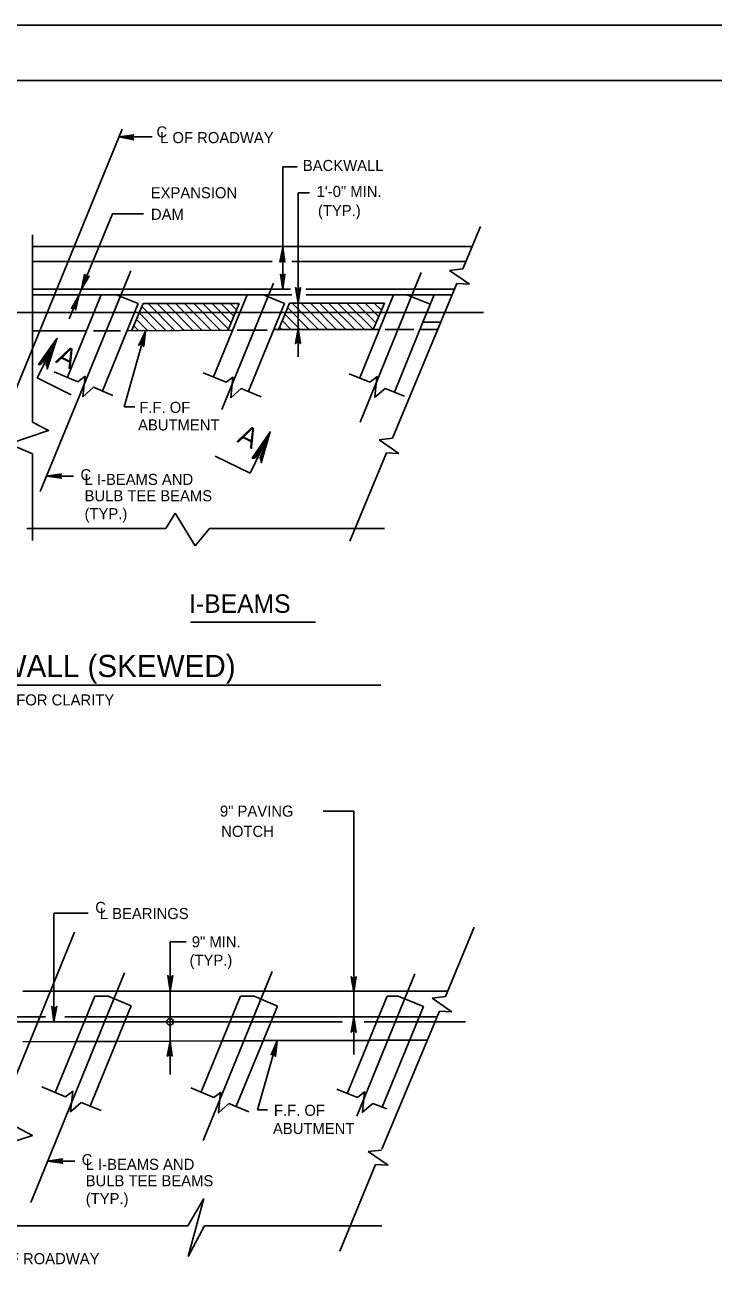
# Model space of a CAD drawing. Extents: x 640058 to 640913, y 299411 to 300005.
# Drawn here: x 640298.9 to 640485.4, y 299663.2 to 300005.4 of the extents above; entities that cross this region are included whole.
import ezdxf

# ---------------------------------------------------------------- set-up
doc = ezdxf.new("R2010")
doc.units = 0
doc.layers.add('1', color=7, linetype='Continuous')
doc.layers.add('PLT-BNDY', color=7, linetype='Continuous')

msp = doc.modelspace()

# ---------------------------------------------------------------- linework, layer by layer
at = {"layer": '1'}
for p, q in [((640097.79, 299990.45), (640883.79, 299990.45)), ((640325.16, 299977.3), (640274.71, 299854.35)), ((640324.26, 299975.2), (640333.26, 299975.2)), ((640368.66, 299945.35), (640368.66, 299967.1)), ((640368.66, 299967.1), (640372.56, 299967.1)), ((640372.86, 299930.2), (640372.86, 299960.05)), ((640372.86, 299960.05), (640375.86, 299960.05)), ((640310.83, 299925.89), (640322.5, 299954.33)), ((640330.9, 299954.33), (640322.5, 299954.33)), ((640417.46, 299939.47), (640422.21, 299950.9)), ((640300.86, 299897.95), (640300.86, 299948.65)), ((640419.97, 299945.5), (640300.86, 299945.5)), ((640368.66, 299933.95), (640368.66, 299945.35)), ((640368.66, 299933.95), (640368.66, 299945.35)), ((640365.82, 299941.45), (640300.86, 299941.45)), ((640302.96, 299879.2), (640327.48, 299938.91)), ((640418.28, 299941.45), (640371.08, 299941.45)), ((640413.84, 299939.03), (640417.46, 299939.47)), ((640419.22, 299935.33), (640413.84, 299939.03)), ((640352.16, 299901.4), (640366.11, 299935.6)), ((640389.64, 299897.96), (640406.18, 299938.44)), ((640398.38, 299893.57), (640415.82, 299935.53)), ((640415.82, 299935.53), (640419.22, 299935.33)), ((640370.79, 299933.95), (640300.86, 299933.95)), ((640371.1, 299932.45), (640300.86, 299932.45)), ((640310.31, 299910.1), (640319.46, 299932.45)), ((640323.66, 299932.45), (640319.46, 299932.45)), ((640323.66, 299932.45), (640329.51, 299930.05)), ((640349.91, 299910.25), (640359.06, 299932.45)), ((640363.41, 299932.45), (640359.06, 299932.45)), ((640363.41, 299932.45), (640369.11, 299930.05)), ((640415.17, 299933.95), (640374.88, 299933.95)), ((640414.54, 299932.45), (640375.02, 299932.45)), ((640389.51, 299909.95), (640398.66, 299932.45)), ((640402.26, 299932.45), (640398.66, 299932.45)), ((640402.26, 299932.45), (640408.63, 299929.93)), ((640409.65, 299932.45), (640406.64, 299925.02)), ((640329.51, 299930.05), (640319.76, 299906.2)), ((640327.8, 299922.85), (640330.8, 299930.05)), ((640336.86, 299922.89), (640330.48, 299929.28)), ((640330.8, 299930.05), (640356.81, 299930.05)), ((640339.46, 299922.77), (640332.18, 299930.05)), ((640341.92, 299922.78), (640334.65, 299930.05)), ((640344.38, 299922.8), (640337.13, 299930.05)), ((640346.84, 299922.81), (640339.6, 299930.05)), ((640349.18, 299922.95), (640342.08, 299930.05)), ((640351.64, 299922.96), (640344.55, 299930.05)), ((640353.93, 299923.14), (640347.02, 299930.05)), ((640354.66, 299924.89), (640349.5, 299930.05)), ((640355.39, 299926.64), (640351.97, 299930.05)), ((640356.81, 299930.05), (640353.86, 299922.97)), ((640356.12, 299928.38), (640354.45, 299930.05)), ((640369.11, 299930.05), (640359.36, 299906.35)), ((640367.49, 299922.97), (640370.44, 299930.2)), ((640375.92, 299922.98), (640369.94, 299928.96)), ((640370.44, 299930.2), (640378.11, 299930.2)), ((640378.39, 299922.99), (640371.18, 299930.2)), ((640371.36, 299930.2), (640374.36, 299930.2)), ((640372.86, 299923), (640372.86, 299930.2)), ((640380.87, 299922.99), (640373.65, 299930.2)), ((640383.34, 299922.99), (640376.13, 299930.2)), ((640376.91, 299930.2), (640396.19, 299930.2)), ((640385.81, 299922.99), (640378.6, 299930.2)), ((640388.28, 299923), (640381.08, 299930.2)), ((640390.76, 299923), (640383.55, 299930.2)), ((640393.2, 299923.03), (640386.03, 299930.2)), ((640393.93, 299924.77), (640388.5, 299930.2)), ((640394.66, 299926.52), (640390.98, 299930.2)), ((640396.19, 299930.2), (640393.19, 299923)), ((640395.39, 299928.27), (640393.45, 299930.2)), ((640396.11, 299930.01), (640395.93, 299930.2)), ((640175.2, 299927.65), (640377.06, 299927.65)), ((640331.93, 299922.87), (640329.02, 299925.78)), ((640334.4, 299922.88), (640329.75, 299927.53)), ((640370.98, 299922.98), (640368.51, 299925.45)), ((640373.45, 299922.98), (640369.22, 299927.21)), ((640376.91, 299927.65), (640423.03, 299927.65)), ((640300.86, 299922.7), (640315.41, 299922.7)), ((640317.43, 299922.7), (640324.74, 299922.7)), ((640325.7, 299902.13), (640331.46, 299922.55)), ((640326.36, 299922.7), (640355.1, 299922.85)), ((640329.47, 299922.86), (640328.29, 299924.03)), ((640356.35, 299922.85), (640364.42, 299922.85)), ((640366.21, 299923), (640394.76, 299923)), ((640368.51, 299922.97), (640367.79, 299923.69)), ((640371.36, 299923), (640374.36, 299923)), ((640372.86, 299915.65), (640372.86, 299923.3)), ((640396.38, 299923), (640404.18, 299923)), ((640406.64, 299925.02), (640398.96, 299906.05)), ((640405.82, 299923), (640410.62, 299923)), ((640406.64, 299925.02), (640411.45, 299925.02)), ((640307.51, 299920.63), (640302.15, 299909.91)), ((640306.71, 299911.6), (640313.16, 299908.9)), ((640302.15, 299909.91), (640311.3, 299905.34)), ((640347.06, 299911.3), (640353.36, 299908.75)), ((640386.66, 299911), (640392.21, 299908.75)), ((640317.36, 299907.4), (640322.61, 299905.15)), ((640357.41, 299907.1), (640362.81, 299904.85)), ((640396.41, 299907.1), (640401.66, 299905)), ((640325.7, 299902.13), (640328.55, 299902.13)), ((640365.21, 299895.35), (640359.86, 299884.14)), ((640394.76, 299893.13), (640398.38, 299893.57)), ((640400.14, 299889.43), (640394.76, 299893.13)), ((640300.86, 299865.85), (640300.86, 299889.4)), ((640350.36, 299888.76), (640359.86, 299884.14)), ((640386.82, 299865.73), (640396.75, 299889.63)), ((640396.75, 299889.63), (640400.14, 299889.43)), ((640304.66, 299883.34), (640312.01, 299883.34)), ((640337, 299869.13), (640339.55, 299873.33)), ((640339.55, 299873.33), (640344.95, 299864.48)), ((640299.35, 299869.13), (640337, 299869.13)), ((640344.95, 299864.48), (640348.85, 299869.13)), ((640348.85, 299869.13), (640396.2, 299869.13)), ((640343.71, 299843.8), (640377.57, 299843.8)), ((640171.38, 299826.75), (640395.26, 299826.75)), ((640387.94, 299792.54), (640379.61, 299792.54)), ((640387.94, 299743.84), (640387.94, 299792.54)), ((640306.68, 299764.99), (640315.93, 299764.99)), ((640306.68, 299735.53), (640306.68, 299764.99)), ((640412.72, 299742.36), (640420.53, 299761.14)), ((640275.18, 299669.17), (640312.23, 299759.85)), ((640338.12, 299757.19), (640342.5, 299757.19)), ((640338.12, 299743.84), (640338.12, 299757.19)), ((640300.38, 299686.57), (640325.79, 299748.84)), ((640347.06, 299703.39), (640365.75, 299749.16)), ((640388.73, 299710.01), (640404.44, 299748.55)), ((640413.34, 299743.84), (640298.28, 299743.84)), ((640338.12, 299735.53), (640338.12, 299743.84)), ((640387.94, 299736.88), (640387.94, 299743.84)), ((640306.98, 299716.42), (640317.73, 299742.47)), ((640321.34, 299742.47), (640317.73, 299742.47)), ((640321.34, 299742.47), (640327.58, 299739.82)), ((640346.58, 299716.57), (640357.17, 299742.47)), ((640360.94, 299742.47), (640357.17, 299742.47)), ((640360.94, 299742.47), (640367.19, 299739.81)), ((640386.18, 299716.27), (640396.93, 299742.47)), ((640399.94, 299742.47), (640396.93, 299742.47)), ((640399.94, 299742.47), (640406.78, 299739.67)), ((640409.1, 299741.92), (640412.72, 299742.36)), ((640414.48, 299738.22), (640409.1, 299741.92)), ((640327.58, 299739.82), (640316.43, 299712.52)), ((640367.19, 299739.81), (640356.03, 299712.67)), ((640395.53, 299701), (640411.09, 299738.42)), ((640406.78, 299739.67), (640395.63, 299712.37)), ((640411.09, 299738.42), (640414.48, 299738.22)), ((640177.72, 299735.53), (640384.72, 299735.53)), ((640304.36, 299736.88), (640183.16, 299736.88)), ((640410.45, 299736.88), (640309.64, 299736.88)), ((640338.12, 299730.37), (640338.12, 299735.53)), ((640387.94, 299726.68), (640387.94, 299736.88)), ((640390.73, 299735.53), (640418.2, 299735.53)), ((640298.28, 299730.07), (640312.68, 299730.22)), ((640312.68, 299730.22), (640323.66, 299730.22)), ((640323.78, 299730.22), (640352.43, 299730.37)), ((640338.12, 299721.26), (640338.12, 299730.3)), ((640352.23, 299730.37), (640363.31, 299730.37)), ((640361.8, 299711.65), (640367.13, 299730.37)), ((640391.99, 299730.44), (640363.33, 299730.44)), ((640392.03, 299730.52), (640403.05, 299730.52)), ((640402.98, 299730.52), (640407.8, 299730.52)), ((640303.38, 299717.92), (640309.83, 299715.22)), ((640343.73, 299717.62), (640350.03, 299715.07)), ((640383.33, 299717.32), (640388.88, 299715.07)), ((640314.03, 299713.72), (640319.43, 299711.47)), ((640354.08, 299713.42), (640359.48, 299711.17)), ((640393.08, 299713.42), (640396.82, 299711.97)), ((640361.8, 299711.65), (640364.54, 299711.65)), ((640391.83, 299700.36), (640395.45, 299700.8)), ((640397.21, 299696.66), (640391.83, 299700.36)), ((640304.97, 299697.81), (640312.32, 299697.81)), ((640384.08, 299673.45), (640393.81, 299696.86)), ((640393.81, 299696.86), (640397.21, 299696.66)), ((640342.96, 299680.27), (640347.29, 299687.66)), ((640347.29, 299687.66), (640343.07, 299671.95)), ((640290.63, 299680.27), (640342.96, 299680.27)), ((640343.07, 299671.95), (640347.48, 299680.27)), ((640347.48, 299680.27), (640395.47, 299680.27))]:
    msp.add_line(p, q, dxfattribs=at)
for points in [[(640328.16, 299974.6), (640328.01, 299974.9), (640324.26, 299975.2), (640328.16, 299974.6), (640328.31, 299974.45), (640324.26, 299975.2), (640328.01, 299975.35), (640328.16, 299975.65), (640324.26, 299975.2), (640328.31, 299975.8), (640328.16, 299975.65)], [(640328.16, 299974.6), (640328.01, 299974.9), (640324.26, 299975.2), (640328.16, 299974.6), (640328.31, 299974.45), (640324.26, 299975.2), (640328.01, 299975.35), (640328.16, 299975.65), (640324.26, 299975.2), (640328.31, 299975.8), (640328.16, 299975.65)], [(640368.21, 299941.45), (640368.51, 299941.6), (640368.66, 299945.35), (640368.21, 299941.45), (640367.91, 299941.3), (640368.66, 299945.35), (640368.81, 299941.6), (640369.11, 299941.45), (640368.66, 299945.35), (640369.26, 299941.3), (640369.11, 299941.45)], [(640315.15, 299937.74), (640315.24, 299937.55), (640314.14, 299933.95), (640315.15, 299937.74), (640314.93, 299937.99), (640314.14, 299933.95), (640315.65, 299937.38), (640315.99, 299937.41), (640314.14, 299933.95), (640316.18, 299937.5), (640315.99, 299937.41)], [(640369.11, 299937.85), (640368.81, 299937.7), (640368.66, 299933.95), (640369.11, 299937.85), (640369.26, 299938), (640368.66, 299933.95), (640368.51, 299937.7), (640368.21, 299937.85), (640368.66, 299933.95), (640368.06, 299938), (640368.21, 299937.85)], [(640312.51, 299928.66), (640312.29, 299928.91), (640313.52, 299932.45), (640312.51, 299928.66), (640312.54, 299928.32), (640313.52, 299932.45), (640312.01, 299929.02), (640311.67, 299928.99), (640313.52, 299932.45), (640311.42, 299928.76), (640311.67, 299928.99)], [(640373.31, 299934.1), (640373.01, 299933.95), (640372.86, 299930.2), (640373.31, 299934.1), (640373.46, 299934.4), (640372.86, 299930.2), (640372.56, 299933.95), (640372.41, 299934.1), (640372.86, 299930.2), (640372.11, 299934.4), (640372.41, 299934.1)], [(640329.96, 299918.95), (640330.26, 299919.1), (640331.46, 299922.55), (640329.96, 299918.95), (640329.66, 299918.8), (640331.46, 299922.55), (640330.56, 299918.95), (640330.86, 299918.65), (640331.46, 299922.55), (640331.01, 299918.5), (640330.86, 299918.65)], [(640338.31, 299922.9), (640338.61, 299922.9)], [(640372.26, 299919.4), (640372.56, 299919.55), (640372.86, 299923.3), (640372.26, 299919.4), (640372.11, 299919.25), (640372.86, 299923.3), (640373.01, 299919.55), (640373.31, 299919.4), (640372.86, 299923.3), (640373.46, 299919.25), (640373.31, 299919.4)], [(640303.06, 299913.58), (640303.68, 299914.16), (640307.5, 299920.63), (640303.06, 299913.58), (640302.46, 299913.6), (640307.5, 299920.63), (640304.56, 299913.53), (640304.84, 299912.92), (640307.5, 299920.63), (640304.82, 299912.32), (640304.84, 299912.92)], [(640317.36, 299907.4), (640314.51, 299904.85), (640315.11, 299910.4), (640313.16, 299908.9)], [(640357.41, 299907.1), (640354.56, 299904.55), (640355.16, 299910.1), (640353.36, 299908.75)], [(640396.41, 299907.1), (640393.56, 299904.7), (640394.16, 299910.25), (640392.21, 299908.75)], [(640300.86, 299889.4), (640294.56, 299892.1), (640305.21, 299895.7), (640300.86, 299897.95)], [(640361.01, 299888.15), (640361.61, 299888.75), (640365.21, 299895.35), (640361.01, 299888.15), (640360.41, 299888.15), (640365.21, 299895.35), (640362.51, 299888.15), (640362.81, 299887.55), (640365.21, 299895.35), (640362.81, 299886.95), (640362.81, 299887.55)], [(640308.56, 299882.89), (640308.41, 299883.19), (640304.66, 299883.34), (640308.56, 299882.89), (640308.71, 299882.74), (640304.66, 299883.34), (640308.41, 299883.49), (640308.56, 299883.79), (640304.66, 299883.34), (640308.71, 299883.94), (640308.56, 299883.79)], [(640338.57, 299747.74), (640338.42, 299747.59), (640338.12, 299743.84), (640338.57, 299747.74), (640338.87, 299748.04), (640338.12, 299743.84), (640337.97, 299747.59), (640337.67, 299747.74), (640338.12, 299743.84), (640337.52, 299748.04), (640337.67, 299747.74)], [(640387.34, 299747.44), (640387.64, 299747.44), (640387.94, 299743.54), (640387.34, 299747.44), (640387.19, 299747.74), (640387.94, 299743.54), (640388.09, 299747.44), (640388.39, 299747.44), (640387.94, 299743.54), (640388.54, 299747.74), (640388.39, 299747.44)], [(640307.13, 299739.43), (640306.98, 299739.28), (640306.68, 299735.53), (640307.13, 299739.43), (640307.43, 299739.73), (640306.68, 299735.53), (640306.53, 299739.28), (640306.23, 299739.43), (640306.68, 299735.53), (640306.08, 299739.73), (640306.23, 299739.43)], [(640388.39, 299732.98), (640388.09, 299733.13), (640387.94, 299736.88), (640388.39, 299732.98), (640388.54, 299732.68), (640387.94, 299736.88), (640387.64, 299733.13), (640387.49, 299732.98), (640387.94, 299736.88), (640387.19, 299732.68), (640387.49, 299732.98)], [(640337.67, 299726.4), (640337.82, 299726.55), (640338.12, 299730.3), (640337.67, 299726.4), (640337.37, 299726.25), (640338.12, 299730.3), (640338.27, 299726.55), (640338.57, 299726.4), (640338.12, 299730.3), (640338.72, 299726.25), (640338.57, 299726.4)], [(640365.63, 299726.77), (640365.93, 299726.77), (640367.13, 299730.37), (640365.63, 299726.77), (640365.48, 299726.62), (640367.13, 299730.37), (640366.38, 299726.77), (640366.53, 299726.47), (640367.13, 299730.37), (640366.68, 299726.17), (640366.53, 299726.47)], [(640314.03, 299713.72), (640311.18, 299711.17), (640311.78, 299716.72), (640309.83, 299715.22)], [(640393.08, 299713.42), (640390.23, 299711.02), (640390.83, 299716.57), (640388.88, 299715.07)], [(640354.08, 299713.42), (640351.23, 299710.87), (640351.83, 299716.42), (640350.03, 299715.07)], [(640294.83, 299699.17), (640290.18, 299701.27), (640300.83, 299704.72), (640296.48, 299707.12)], [(640308.87, 299697.36), (640308.72, 299697.66), (640304.97, 299697.81), (640308.87, 299697.36), (640309.02, 299697.21), (640304.97, 299697.81), (640308.72, 299697.96), (640308.87, 299698.26), (640304.97, 299697.81), (640309.02, 299698.41), (640308.87, 299698.26)]]:
    msp.add_lwpolyline(points, dxfattribs=at)
msp.add_lwpolyline([(640370.44, 299930.2), (640367.49, 299922.97), (640393.19, 299923), (640396.19, 299930.2)], close=True, dxfattribs=at)
msp.add_circle((640338.12, 299735.53), 0.901, dxfattribs=at)
at = {"layer": 'PLT-BNDY'}
msp.add_lwpolyline([(640057.79, 299411.45), (640898.79, 299411.45), (640898.79, 300005.45), (640057.79, 300005.45)], close=True, dxfattribs=at)

# ---------------------------------------------------------------- texts
at = {"layer": '1'}
for s, height, p in [('C', 3, (640334.45, 299975.07)), ('L OF ROADWAY', 2.9999, (640335.43, 299973.52)), ('BACKWALL', 3, (640374.1, 299965.97)), ('EXPANSION', 3, (640332.9, 299958.58)), ('1\'-0" MIN.', 3, (640377.85, 299958.93)), ('(TYP.)', 3, (640378.19, 299953.77)), ('DAM', 3, (640332.95, 299952.74)), ('F.F. OF', 3, (640329.8, 299900.45)), ('ABUTMENT', 3, (640329.46, 299895.7)), ('C', 3, (640313.88, 299882.24)), ('L I-BEAMS AND', 2.9999, (640314.97, 299880.95)), ('BULB TEE BEAMS', 2.9999, (640314.97, 299876.51)), ('(TYP.)', 3, (640314.97, 299871.66)), ('I-BEAMS', 5, (640343.29, 299846.3)), ('ABUTMENT PLAN - WITH BACKWALL (SKEWED)', 6, (640172.67, 299828.91)), ('NOTE: END DIAPHRAGMS NOT SHOWN FOR CLARITY', 2.9999, (640219.35, 299821.22)), ('9" PAVING', 3, (640351.64, 299791.09)), ('NOTCH', 3, (640351.99, 299785.62)), ('C', 3, (640317.86, 299765.01)), ('L BEARINGS', 3, (640319.1, 299763.36)), ('9" MIN.', 3, (640344.01, 299755.7)), ('(TYP.)', 3, (640343.41, 299750.73)), ('F.F. OF', 3, (640366.27, 299710.05)), ('ABUTMENT', 3, (640366, 299705.13)), ('C', 3, (640314.19, 299696.71)), ('L I-BEAMS AND', 2.9999, (640315.28, 299695.43)), ('BULB TEE BEAMS', 2.9999, (640315.28, 299690.99)), ('(TYP.)', 3, (640315.28, 299686.14)), ('L OF ROADWAY', 2.9999, (640288.26, 299669.88))]:
    msp.add_text(s, height=height, dxfattribs=at).set_placement(p)
for p in [(640306.87, 299914.24), (640356.04, 299892.7)]:
    msp.add_text('A', height=5.4, rotation=334, dxfattribs=at).set_placement(p)

doc.saveas('drawing.dxf')
